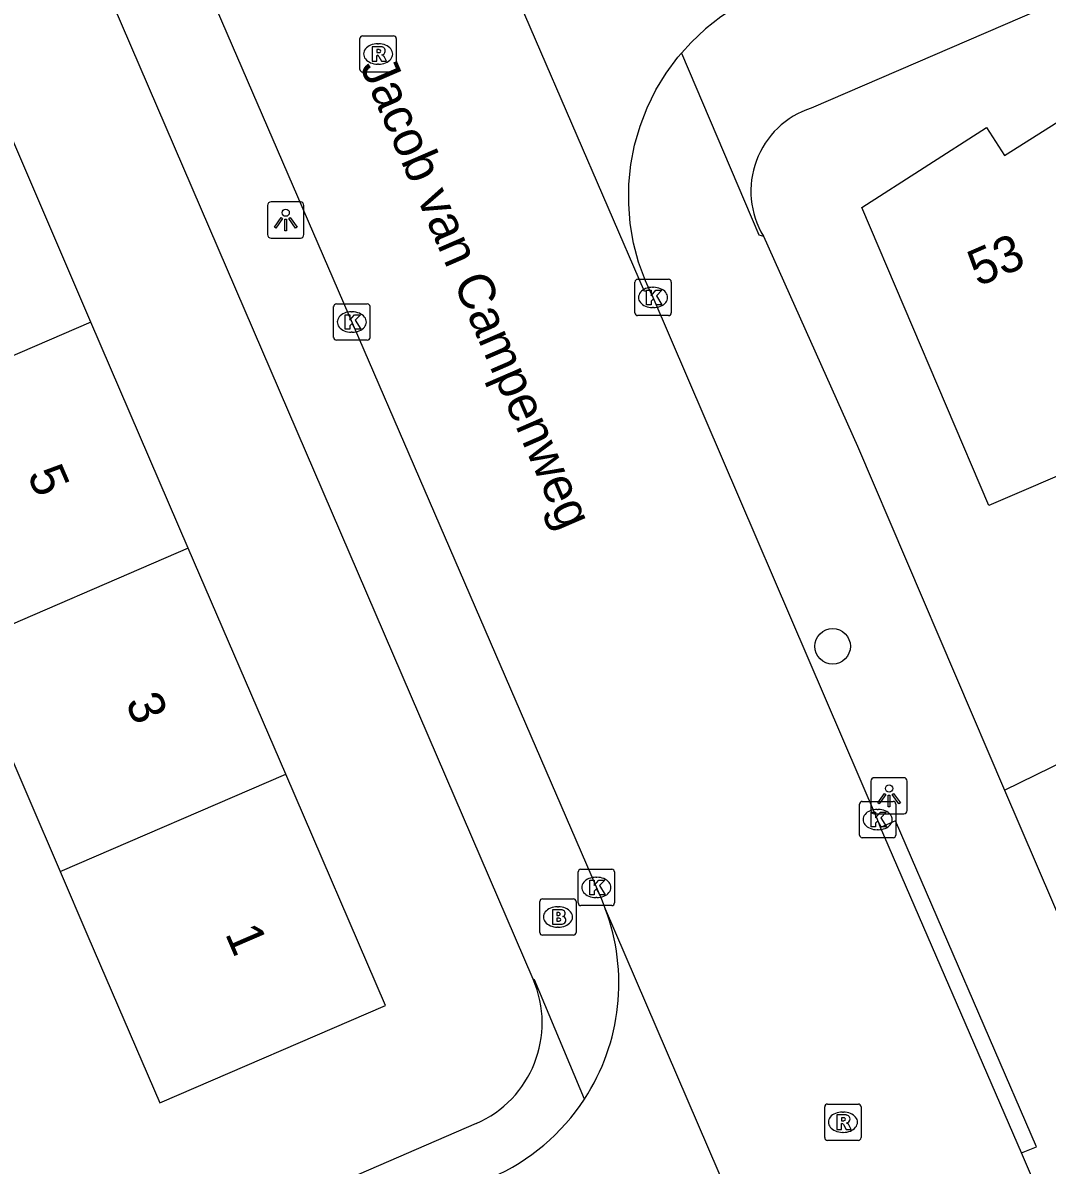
# Model space of a CAD drawing. Extents: x 159353 to 160616, y 385893 to 387321.
# Drawn here: x 159577.86 to 159606.08, y 386179.76 to 386211.22 of the extents above; entities that cross this region are included whole.
import ezdxf

# ---------------------------------------------------------------- set-up
doc = ezdxf.new("R2010")
doc.units = 0
for name, color, linetype in [('IMGEO_Boom', 7, 'Continuous'), ('IMGEO_Brandkraan', 7, 'Continuous'), ('IMGEO_Kolk', 7, 'Continuous'), ('IMGEO_Lichtpunt', 7, 'Continuous'), ('IMGEO_Muur', 7, 'Continuous'), ('IMGEO_Openbare_ruimte_label', 7, 'Continuous'), ('IMGEO_Pand', 7, 'Continuous'), ('IMGEO_Pand_nummerreeks', 7, 'Continuous'), ('IMGEO_Rijbaan_lokaal_gesloten', 7, 'Continuous'), ('IMGEO_Rijbaan_lokaal_open', 7, 'Continuous'), ('IMGEO_Rioolput', 7, 'Continuous'), ('IMGEO_Voetpad_open', 7, 'Continuous')]:
    doc.layers.add(name, color=color, linetype=linetype)

msp = doc.modelspace()

# ---------------------------------------------------------------- linework, layer by layer
at = {"layer": 'IMGEO_Boom'}
msp.add_circle((159600.17, 386194.051), 0.489, dxfattribs=at)
at = {"layer": 'IMGEO_Brandkraan'}
for p, q in [((159592.101, 386186.17), (159592.101, 386187.022)), ((159592.176, 386187.096), (159593.028, 386187.096)), ((159592.589, 386186.876), (159592.614, 386186.876)), ((159593.102, 386187.022), (159593.102, 386186.17)), ((159592.612, 386186.316), (159592.587, 386186.316)), ((159593.028, 386186.096), (159592.176, 386186.096))]:
    msp.add_line(p, q, dxfattribs=at)
for points in [[(159592.101, 386186.17), (159592.101, 386187.022)], [(159592.176, 386187.096), (159593.028, 386187.096)], [(159593.102, 386187.022), (159593.102, 386186.17)], [(159592.449, 386186.796), (159592.449, 386186.396), (159592.662, 386186.396)], [(159592.68, 386186.796), (159592.449, 386186.796)], [(159592.628, 386186.715), (159592.574, 386186.715), (159592.574, 386186.639)], [(159592.574, 386186.639), (159592.627, 386186.639)], [(159592.636, 386186.563), (159592.574, 386186.563), (159592.574, 386186.482)], [(159592.574, 386186.482), (159592.636, 386186.482)], [(159593.028, 386186.096), (159592.176, 386186.096)]]:
    msp.add_lwpolyline(points, dxfattribs=at)
for centre, radius, start, end in [((159592.178, 386187.02), 0.0765, 91.552, 178.448), ((159592.178, 386187.02), 0.0765, 91.552, 178.448), ((159593.026, 386187.02), 0.0765, 1.552, 88.448), ((159593.026, 386187.02), 0.0765, 1.552, 88.448), ((159592.629, 386186.677), 0.0379, 267.8285, 90.9355), ((159592.637, 386186.522), 0.0404, 269.8759, 90.5077), ((159592.684, 386186.651), 0.145, 59.4692, 91.5367), ((159592.709, 386186.698), 0.0922, 285.5137, 58.1501), ((159592.714, 386186.506), 0.105, 301.3115, 78.989), ((159592.668, 386186.647), 0.251, 268.6676, 293.5347), ((159592.178, 386186.172), 0.0765, 181.552, 268.448), ((159592.178, 386186.172), 0.0765, 181.552, 268.448), ((159593.026, 386186.172), 0.0765, 271.552, 358.448), ((159593.026, 386186.172), 0.0765, 271.552, 358.448)]:
    msp.add_arc(centre, radius, start, end, dxfattribs=at)
for centre, major_axis, ratio, start_param, end_param in [((159592.588, 386186.596), (-0.387, 0.002), 0.722429, 4.712389, 7.853982), ((159592.613, 386186.596), (-0.39, 0.002), 0.717154, 1.570796, 4.712389)]:
    msp.add_ellipse(centre, major_axis=major_axis, ratio=ratio, start_param=start_param, end_param=end_param, dxfattribs=at)
at = {"layer": 'IMGEO_Kolk'}
for p, q in [((159594.797, 386204.159), (159595.649, 386204.159)), ((159594.722, 386203.233), (159594.722, 386204.085)), ((159595.21, 386203.939), (159595.235, 386203.939)), ((159595.723, 386204.085), (159595.723, 386203.233)), ((159586.423, 386202.556), (159586.423, 386203.408)), ((159586.498, 386203.482), (159587.35, 386203.482)), ((159586.911, 386203.262), (159586.936, 386203.262)), ((159587.424, 386203.408), (159587.424, 386202.556)), ((159595.233, 386203.379), (159595.208, 386203.379)), ((159595.649, 386203.159), (159594.797, 386203.159)), ((159586.934, 386202.702), (159586.909, 386202.702)), ((159587.35, 386202.482), (159586.498, 386202.482)), ((159600.91, 386188.853), (159600.91, 386189.705)), ((159600.985, 386189.779), (159601.837, 386189.779)), ((159601.911, 386189.705), (159601.911, 386188.853)), ((159601.398, 386189.559), (159601.423, 386189.559)), ((159601.837, 386188.779), (159600.985, 386188.779)), ((159601.421, 386188.999), (159601.396, 386188.999)), ((159593.159, 386186.984), (159593.159, 386187.836)), ((159593.234, 386187.91), (159594.086, 386187.91)), ((159594.16, 386187.836), (159594.16, 386186.984)), ((159593.647, 386187.69), (159593.672, 386187.69)), ((159594.086, 386186.91), (159593.234, 386186.91)), ((159593.67, 386187.13), (159593.645, 386187.13))]:
    msp.add_line(p, q, dxfattribs=at)
for points in [[(159594.797, 386204.159), (159595.649, 386204.159)], [(159594.722, 386203.233), (159594.722, 386204.085)], [(159595.043, 386203.859), (159595.166, 386203.859), (159595.166, 386203.708), (159595.296, 386203.859), (159595.46, 386203.859), (159595.314, 386203.708), (159595.467, 386203.459), (159595.315, 386203.459), (159595.23, 386203.623), (159595.166, 386203.556), (159595.166, 386203.459), (159595.043, 386203.459), (159595.043, 386203.859)], [(159595.723, 386204.085), (159595.723, 386203.233)], [(159586.423, 386202.556), (159586.423, 386203.408)], [(159586.498, 386203.482), (159587.35, 386203.482)], [(159587.424, 386203.408), (159587.424, 386202.556)], [(159586.744, 386203.182), (159586.867, 386203.182), (159586.867, 386203.031), (159586.997, 386203.182), (159587.161, 386203.182), (159587.015, 386203.031), (159587.168, 386202.782), (159587.016, 386202.782), (159586.931, 386202.946), (159586.867, 386202.879), (159586.867, 386202.782), (159586.744, 386202.782), (159586.744, 386203.182)], [(159595.649, 386203.159), (159594.797, 386203.159)], [(159587.35, 386202.482), (159586.498, 386202.482)], [(159600.91, 386188.853), (159600.91, 386189.705)], [(159600.985, 386189.779), (159601.837, 386189.779)], [(159601.911, 386189.705), (159601.911, 386188.853)], [(159601.231, 386189.479), (159601.354, 386189.479), (159601.354, 386189.328), (159601.484, 386189.479), (159601.648, 386189.479), (159601.502, 386189.328), (159601.655, 386189.079), (159601.503, 386189.079), (159601.418, 386189.243), (159601.354, 386189.176), (159601.354, 386189.079), (159601.231, 386189.079), (159601.231, 386189.479)], [(159601.837, 386188.779), (159600.985, 386188.779)], [(159593.159, 386186.984), (159593.159, 386187.836)], [(159593.234, 386187.91), (159594.086, 386187.91)], [(159594.16, 386187.836), (159594.16, 386186.984)], [(159593.48, 386187.61), (159593.603, 386187.61), (159593.603, 386187.459), (159593.733, 386187.61), (159593.897, 386187.61), (159593.751, 386187.459), (159593.904, 386187.21), (159593.752, 386187.21), (159593.667, 386187.374), (159593.603, 386187.307), (159593.603, 386187.21), (159593.48, 386187.21), (159593.48, 386187.61)], [(159594.086, 386186.91), (159593.234, 386186.91)]]:
    msp.add_lwpolyline(points, dxfattribs=at)
for centre, start, end in [((159594.799, 386204.083), 91.552, 178.448), ((159594.799, 386204.083), 91.552, 178.448), ((159595.647, 386204.083), 1.552, 88.448), ((159595.647, 386204.083), 1.552, 88.448), ((159586.5, 386203.406), 91.552, 178.448), ((159586.5, 386203.406), 91.552, 178.448), ((159587.348, 386203.406), 1.552, 88.448), ((159587.348, 386203.406), 1.552, 88.448), ((159594.799, 386203.235), 181.552, 268.448), ((159594.799, 386203.235), 181.552, 268.448), ((159595.647, 386203.235), 271.552, 358.448), ((159595.647, 386203.235), 271.552, 358.448), ((159586.5, 386202.558), 181.552, 268.448), ((159586.5, 386202.558), 181.552, 268.448), ((159587.348, 386202.558), 271.552, 358.448), ((159587.348, 386202.558), 271.552, 358.448), ((159600.987, 386189.703), 91.552, 178.448), ((159600.987, 386189.703), 91.552, 178.448), ((159601.835, 386189.703), 1.552, 88.448), ((159601.835, 386189.703), 1.552, 88.448), ((159600.987, 386188.855), 181.552, 268.448), ((159600.987, 386188.855), 181.552, 268.448), ((159601.835, 386188.855), 271.552, 358.448), ((159601.835, 386188.855), 271.552, 358.448), ((159593.236, 386187.834), 91.552, 178.448), ((159593.236, 386187.834), 91.552, 178.448), ((159594.084, 386187.834), 1.552, 88.448), ((159594.084, 386187.834), 1.552, 88.448), ((159593.236, 386186.986), 181.552, 268.448), ((159593.236, 386186.986), 181.552, 268.448), ((159594.084, 386186.986), 271.552, 358.448), ((159594.084, 386186.986), 271.552, 358.448)]:
    msp.add_arc(centre, 0.0765, start, end, dxfattribs=at)
for centre, major_axis, ratio, start_param, end_param in [((159595.209, 386203.659), (-0.387, 0.002), 0.722429, 4.712389, 7.853982), ((159595.234, 386203.659), (-0.39, 0.002), 0.717154, 1.570796, 4.712389), ((159586.91, 386202.982), (-0.387, 0.002), 0.722429, 4.712389, 7.853982), ((159586.935, 386202.982), (-0.39, 0.002), 0.717154, 1.570796, 4.712389), ((159601.397, 386189.279), (-0.387, 0.002), 0.722429, 4.712389, 7.853982), ((159601.422, 386189.279), (-0.39, 0.002), 0.717154, 1.570796, 4.712389), ((159593.646, 386187.41), (-0.387, 0.002), 0.722429, 4.712389, 7.853982), ((159593.671, 386187.41), (-0.39, 0.002), 0.717154, 1.570796, 4.712389)]:
    msp.add_ellipse(centre, major_axis=major_axis, ratio=ratio, start_param=start_param, end_param=end_param, dxfattribs=at)
at = {"layer": 'IMGEO_Lichtpunt'}
for p, q in [((159584.603, 386206.196), (159584.603, 386205.389)), ((159584.603, 386206.196), (159584.603, 386205.389)), ((159585.505, 386206.291), (159584.697, 386206.291)), ((159585.505, 386206.291), (159584.697, 386206.291)), ((159585.599, 386205.389), (159585.599, 386206.196)), ((159585.599, 386205.389), (159585.599, 386206.196)), ((159584.697, 386205.295), (159585.505, 386205.295)), ((159584.697, 386205.295), (159585.505, 386205.295)), ((159601.226, 386190.337), (159601.226, 386189.53)), ((159601.226, 386190.337), (159601.226, 386189.53)), ((159602.128, 386190.432), (159601.32, 386190.432)), ((159602.128, 386190.432), (159601.32, 386190.432)), ((159602.222, 386189.53), (159602.222, 386190.337)), ((159602.222, 386189.53), (159602.222, 386190.337)), ((159601.32, 386189.436), (159602.128, 386189.436)), ((159601.32, 386189.436), (159602.128, 386189.436))]:
    msp.add_line(p, q, dxfattribs=at)
for points in [[(159584.977, 386205.86), (159585.016, 386205.832), (159584.828, 386205.57), (159584.79, 386205.597), (159584.977, 386205.86)], [(159585.079, 386205.812), (159585.126, 386205.812), (159585.126, 386205.49), (159585.079, 386205.49), (159585.079, 386205.812)], [(159585.189, 386205.832), (159585.227, 386205.859), (159585.414, 386205.597), (159585.375, 386205.569), (159585.189, 386205.832)], [(159601.6, 386190.001), (159601.639, 386189.973), (159601.451, 386189.711), (159601.413, 386189.738), (159601.6, 386190.001)], [(159601.812, 386189.973), (159601.85, 386190), (159602.037, 386189.738), (159601.998, 386189.71), (159601.812, 386189.973)], [(159601.702, 386189.953), (159601.749, 386189.953), (159601.749, 386189.631), (159601.702, 386189.631), (159601.702, 386189.953)]]:
    msp.add_lwpolyline(points, dxfattribs=at)
for centre in [(159585.102, 386205.994), (159601.725, 386190.135)]:
    msp.add_circle(centre, 0.0994, dxfattribs=at)
for centre, start, end in [((159584.697, 386206.196), 90, 180), ((159584.697, 386206.196), 90, 180), ((159585.505, 386206.196), 0, 90), ((159585.505, 386206.196), 0, 90), ((159584.697, 386205.389), 180, 270), ((159584.697, 386205.389), 180, 270), ((159585.505, 386205.389), 270, 0), ((159585.505, 386205.389), 270, 360), ((159601.32, 386190.337), 90, 180), ((159601.32, 386190.337), 90, 180), ((159602.128, 386190.337), 0, 90), ((159602.128, 386190.337), 0, 90), ((159601.32, 386189.53), 180, 270), ((159601.32, 386189.53), 180, 270), ((159602.128, 386189.53), 270, 0), ((159602.128, 386189.53), 270, 360)]:
    msp.add_arc(centre, 0.0946, start, end, dxfattribs=at)
at = {"layer": 'IMGEO_Muur'}
msp.add_lwpolyline([(159600.855, 386199.563), (159604.904, 386190.092)], dxfattribs=at)
at = {"layer": 'IMGEO_Pand'}
for points in [[(159579.733, 386202.982), (159577.048, 386209.211)], [(159609.97, 386200.288), (159604.475, 386197.925), (159600.976, 386206.139), (159604.405, 386208.338), (159604.909, 386207.565), (159606.375, 386208.496)], [(159579.733, 386202.982), (159573.519, 386200.302)], [(159582.418, 386196.754), (159579.733, 386202.982)], [(159582.418, 386196.754), (159576.203, 386194.074)], [(159585.102, 386190.527), (159582.418, 386196.754)], [(159576.203, 386194.074), (159578.888, 386187.847)], [(159578.888, 386187.847), (159585.102, 386190.527)], [(159578.888, 386187.847), (159579.653, 386186.072), (159581.632, 386181.48), (159587.847, 386184.159), (159585.102, 386190.527)]]:
    msp.add_lwpolyline(points, dxfattribs=at)
at = {"layer": 'IMGEO_Rijbaan_lokaal_gesloten'}
for points in [[(159572.998, 386235.252), (159581.946, 386214.493), (159593.802, 386187.082), (159593.907, 386186.821)], [(159595.12, 386203.87), (159594.985, 386203.82), (159587.984, 386220.031)], [(159601.493, 386189.065), (159601.41, 386189.278), (159595.222, 386203.658), (159595.12, 386203.87)], [(159605.373, 386180.099), (159601.493, 386189.065)], [(159593.907, 386186.821), (159600.42, 386171.678)], [(159617.137, 386152.722), (159605.373, 386180.099)]]:
    msp.add_lwpolyline(points, dxfattribs=at)
at = {"layer": 'IMGEO_Rijbaan_lokaal_open'}
for points in [[(159601.918, 386213.607), (159598.031, 386211.942), (159597.55, 386211.688), (159597.094, 386211.391), (159596.666, 386211.055), (159596.27, 386210.683), (159596.01, 386210.39)], [(159595.12, 386203.87), (159595.01, 386204.12), (159594.825, 386204.632), (159594.686, 386205.158), (159594.595, 386205.694), (159594.553, 386206.236), (159594.558, 386206.78), (159594.613, 386207.322), (159594.715, 386207.856), (159594.865, 386208.379), (159595.061, 386208.886), (159595.302, 386209.374), (159595.585, 386209.839), (159595.909, 386210.276), (159596.01, 386210.39)]]:
    msp.add_lwpolyline(points, dxfattribs=at)
for centre, radius, start, end in [((159588.448, 386184.767), 5.832, 326.8624, 20.618), ((159588.445, 386184.771), 5.837, 293.5873, 326.8451)]:
    msp.add_arc(centre, radius, start, end, dxfattribs=at)
at = {"layer": 'IMGEO_Rioolput'}
for p, q in [((159587.147, 386209.94), (159587.147, 386210.792)), ((159587.222, 386210.866), (159588.074, 386210.866)), ((159588.148, 386210.792), (159588.148, 386209.94)), ((159587.635, 386210.646), (159587.66, 386210.646)), ((159588.074, 386209.866), (159587.222, 386209.866)), ((159587.658, 386210.086), (159587.633, 386210.086)), ((159599.952, 386180.518), (159599.952, 386181.37)), ((159600.027, 386181.444), (159600.879, 386181.444)), ((159600.44, 386181.224), (159600.465, 386181.224)), ((159600.953, 386181.37), (159600.953, 386180.518)), ((159600.463, 386180.664), (159600.438, 386180.664)), ((159600.879, 386180.444), (159600.027, 386180.444))]:
    msp.add_line(p, q, dxfattribs=at)
for points in [[(159587.147, 386209.94), (159587.147, 386210.792)], [(159587.222, 386210.866), (159588.074, 386210.866)], [(159588.148, 386210.792), (159588.148, 386209.94)], [(159587.736, 386210.564), (159587.484, 386210.566), (159587.484, 386210.166)], [(159587.662, 386210.485), (159587.608, 386210.485), (159587.608, 386210.404)], [(159587.484, 386210.166), (159587.608, 386210.166), (159587.608, 386210.328), (159587.619, 386210.328)], [(159587.608, 386210.404), (159587.66, 386210.404)], [(159587.666, 386210.299), (159587.737, 386210.166), (159587.877, 386210.166), (159587.812, 386210.292)], [(159588.074, 386209.866), (159587.222, 386209.866)], [(159599.952, 386180.518), (159599.952, 386181.37)], [(159600.027, 386181.444), (159600.879, 386181.444)], [(159600.953, 386181.37), (159600.953, 386180.518)], [(159600.541, 386181.142), (159600.289, 386181.144), (159600.289, 386180.744)], [(159600.289, 386180.744), (159600.413, 386180.744), (159600.413, 386180.906), (159600.424, 386180.906)], [(159600.467, 386181.063), (159600.413, 386181.063), (159600.413, 386180.982)], [(159600.413, 386180.982), (159600.465, 386180.982)], [(159600.471, 386180.877), (159600.542, 386180.744), (159600.682, 386180.744), (159600.617, 386180.87)], [(159600.879, 386180.444), (159600.027, 386180.444)]]:
    msp.add_lwpolyline(points, dxfattribs=at)
for centre, radius, start, end in [((159587.224, 386210.79), 0.0765, 91.552, 178.448), ((159587.224, 386210.79), 0.0765, 91.552, 178.448), ((159588.072, 386210.79), 0.0765, 1.552, 88.448), ((159588.072, 386210.79), 0.0765, 1.552, 88.448), ((159587.668, 386210.389), 0.0964, 77.0061, 93.1865), ((159587.682, 386210.446), 0.0378, 276.6634, 79.6772), ((159587.735, 386210.454), 0.109, 350.3612, 89.416), ((159587.733, 386210.454), 0.112, 277.5842, 350.9817), ((159587.618, 386210.275), 0.0533, 26.0293, 88.6989), ((159587.644, 386210.593), 0.19, 274.7715, 282.9687), ((159587.717, 386210.239), 0.108, 29.5134, 73.7905), ((159587.224, 386209.942), 0.0765, 181.552, 268.448), ((159587.224, 386209.942), 0.0765, 181.552, 268.448), ((159588.072, 386209.942), 0.0765, 271.552, 358.448), ((159588.072, 386209.942), 0.0765, 271.552, 358.448), ((159600.029, 386181.368), 0.0765, 91.552, 178.448), ((159600.029, 386181.368), 0.0765, 91.552, 178.448), ((159600.877, 386181.368), 0.0765, 1.552, 88.448), ((159600.877, 386181.368), 0.0765, 1.552, 88.448), ((159600.423, 386180.853), 0.0533, 26.0293, 88.6989), ((159600.449, 386181.171), 0.19, 274.7715, 282.9687), ((159600.473, 386180.967), 0.0964, 77.0061, 93.1865), ((159600.487, 386181.024), 0.0378, 276.6634, 79.6772), ((159600.54, 386181.032), 0.109, 350.3612, 89.416), ((159600.538, 386181.032), 0.112, 277.5842, 350.9817), ((159600.522, 386180.817), 0.108, 29.5134, 73.7905), ((159600.029, 386180.52), 0.0765, 181.552, 268.448), ((159600.029, 386180.52), 0.0765, 181.552, 268.448), ((159600.877, 386180.52), 0.0765, 271.552, 358.448), ((159600.877, 386180.52), 0.0765, 271.552, 358.448)]:
    msp.add_arc(centre, radius, start, end, dxfattribs=at)
for centre, major_axis, ratio, start_param, end_param in [((159587.634, 386210.366), (-0.387, 0.002), 0.722429, 4.712389, 7.853982), ((159587.659, 386210.366), (-0.39, 0.002), 0.717154, 1.570796, 4.712389), ((159600.439, 386180.944), (-0.387, 0.002), 0.722429, 4.712389, 7.853982), ((159600.464, 386180.944), (-0.39, 0.002), 0.717154, 1.570796, 4.712389)]:
    msp.add_ellipse(centre, major_axis=major_axis, ratio=ratio, start_param=start_param, end_param=end_param, dxfattribs=at)
at = {"layer": 'IMGEO_Voetpad_open'}
for points in [[(159700.471, 386252.381), (159694.949, 386250), (159599.575, 386208.876)], [(159591.919, 386184.881), (159570.226, 386235.195)], [(159596.01, 386210.39), (159598.133, 386205.382), (159598.261, 386205.346)], [(159598.261, 386205.346), (159600.855, 386199.563), (159604.904, 386190.092)], [(159604.904, 386190.092), (159606.627, 386190.935)], [(159604.904, 386190.092), (159608.419, 386181.908)], [(159605.373, 386180.099), (159605.785, 386180.265), (159601.898, 386189.245), (159601.493, 386189.065)], [(159593.332, 386181.579), (159591.954, 386184.864), (159591.919, 386184.881)], [(159590.345, 386180.906), (159571.098, 386172.573)]]:
    msp.add_lwpolyline(points, dxfattribs=at)
for centre, radius, start, end in [((159600.326, 386206.587), 2.409, 108.1601, 211.0056), ((159589.143, 386183.681), 3.024, 293.4165, 23.3789)]:
    msp.add_arc(centre, radius, start, end, dxfattribs=at)

# ---------------------------------------------------------------- texts
at = {"layer": 'IMGEO_Openbare_ruimte_label'}
msp.add_text('Jacob van Campenweg', height=1, rotation=293.3866, dxfattribs=at).set_placement((159587.142, 386210.023))
at = {"layer": 'IMGEO_Pand_nummerreeks'}
for s, rotation, p in [('53', 23.3389, (159604.175, 386203.947)), ('5', 293.3183, (159577.972, 386198.781)), ('3', 293.3183, (159580.674, 386192.514)), ('1', 293.3183, (159583.42, 386186.142))]:
    msp.add_text(s, height=1, rotation=rotation, dxfattribs=at).set_placement(p)

doc.saveas('drawing.dxf')
